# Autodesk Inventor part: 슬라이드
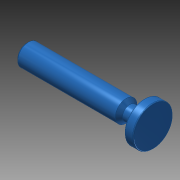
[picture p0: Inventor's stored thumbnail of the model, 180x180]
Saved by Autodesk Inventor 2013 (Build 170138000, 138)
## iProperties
Company: 한국ATC센터
Created: 2015-12
Part Number: 슬라이드
Document SubType Name: Modeling
Designer: mdu
Density: 7.86 g/cm^3
Mass: 68.0563 g
Surface Area: 34.7349 cm^2
Volume: 8.65856 cm^3
Material: 강철, 연강
Author: mdu
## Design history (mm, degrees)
sketch "스케치1"
  geometry: L1 (-27.5, 0)-(27.5, 0); L2 (27.5, 0)-(27.5, 11); L3 (27.5, 11)-(22.5, 11); L4 (22.5, 11)-(22.5, 4); L5 (22.5, 4)-(14.5, 4); L6 (14.5, 4)-(12.5, 6); L7 (12.5, 6)-(-27.5, 6); L8 (-27.5, 6)-(-27.5, 0); 1 further point
  constraints: 16 end point, 4 parallel, 2 midpoint, 2 perpendicular, 1 horizontal
  dimensions: "d0" = 55 distance of L1.start L1.end; "d1" = 12 diameter of L7 L1; "d2" = 22 diameter of L3 L1; "d3" = 5 distance of L2.end L3.end; "d4" = 8 diameter of L5 L1; "d5" = 135 deg angle of L6 L5; "d6" = 15 distance from line of L2 L6.end
revolve "회전1" sketch "스케치1" stored, may be unused: angle "d7" = 90 deg
chamfer "모따기1" distance "d8" = 1; stored, may be unused: second distance "d9" = 2, angle "d10" = 45 deg
fillet "모깎기1" dims "d11" = 0.5
node "솔리드1"
